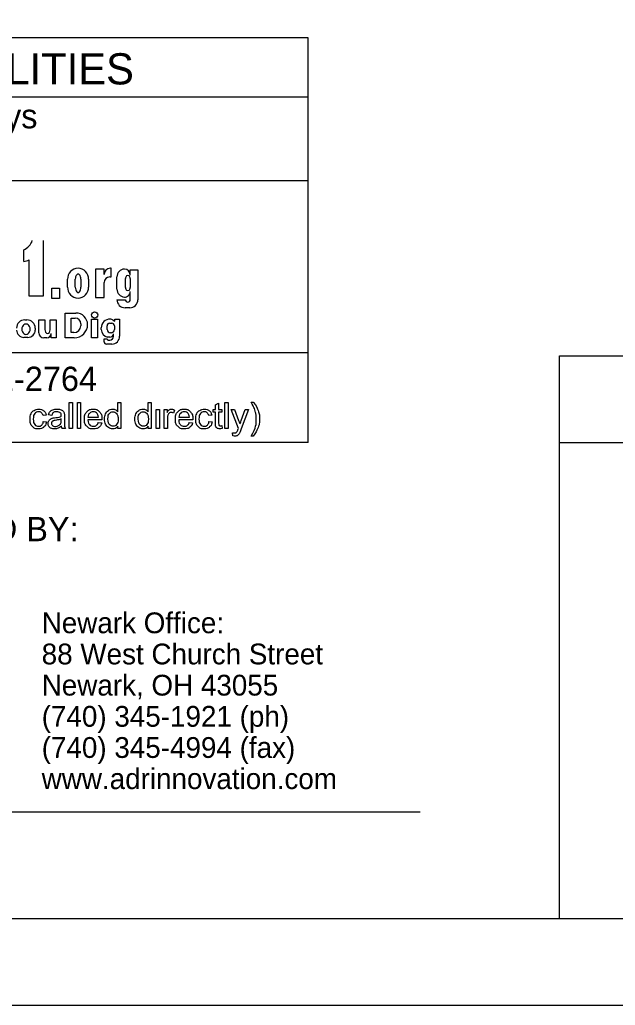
# Model space of a CAD drawing. Extents: x -6.4 to 34, y -1.2 to 22.
# Drawn here: x 5.59 to 9.02, y 0 to 5.69 of the extents above; entities that cross this region are included whole.
import ezdxf

# ---------------------------------------------------------------- set-up
doc = ezdxf.new("R2010")
doc.units = 0
for name, color, linetype in [('GM_X_County', 7, 'Continuous'), ('GM_X_Section', 7, 'Continuous'), ('GM_X_Township', 7, 'Continuous')]:
    doc.layers.add(name, color=color, linetype=linetype)

msp = doc.modelspace()

# ---------------------------------------------------------------- linework, layer by layer
at = {"layer": 'GM_X_County'}
msp.add_lwpolyline([(1.5, 21.5), (33.5, 21.5), (33.5, 0.5), (1.5, 0.5)], close=True, dxfattribs=at)
at = {"layer": 'GM_X_Section'}
msp.add_lwpolyline([(0, 0), (34, 0), (34, 22), (0, 22)], close=True, dxfattribs=at)
at = {"layer": 'GM_X_Township'}
for p, q in [((7.25, 5.5875), (3, 5.5875)), ((7.25, 3.25), (7.25, 5.5875)), ((3, 5.2459), (7.25, 5.2459)), ((3, 4.7625), (7.25, 4.7625)), ((5.72, 4.4158), (5.72, 4.0959)), ((5.6084, 4.2951), (5.6084, 4.3633)), ((5.6407, 4.0959), (5.6407, 4.3045)), ((6.0718, 4.2507), (6.023, 4.2507)), ((6.023, 4.2507), (6.023, 4.0878)), ((6.0718, 4.2192), (6.0718, 4.2507)), ((6.1125, 4.2559), (6.1085, 4.2559)), ((6.1125, 4.206), (6.1125, 4.2559)), ((6.2233, 4.2166), (6.2233, 4.2476)), ((6.2233, 4.2476), (6.2669, 4.2476)), ((6.2669, 4.2476), (6.2669, 4.0747)), ((5.8609, 4.1476), (5.8609, 4.193)), ((5.906, 4.1468), (5.906, 4.193)), ((5.9381, 4.193), (5.9381, 4.1468)), ((5.9831, 4.193), (5.9831, 4.1476)), ((6.0718, 4.0878), (6.0718, 4.173)), ((6.1048, 4.206), (6.1125, 4.206)), ((6.1464, 4.1361), (6.1464, 4.2058)), ((6.1948, 4.1455), (6.1948, 4.1965)), ((6.2233, 4.1965), (6.2233, 4.1455)), ((5.7681, 4.1409), (5.7681, 4.0808)), ((6.2233, 4.0747), (6.2233, 4.1211)), ((5.72, 4.0959), (5.6407, 4.0959)), ((6.023, 4.0878), (6.0718, 4.0878)), ((6.1464, 4.0747), (6.1948, 4.0747)), ((5.8468, 3.9978), (5.9091, 3.9978)), ((5.8468, 3.855), (5.8468, 3.9978)), ((6.2201, 4.028), (6.1932, 4.028)), ((5.615, 3.9579), (5.6272, 3.9579)), ((5.6952, 3.9579), (5.7299, 3.9579)), ((5.6952, 3.8834), (5.6952, 3.9579)), ((5.7299, 3.9579), (5.7299, 3.9026)), ((5.7613, 3.9009), (5.7613, 3.9579)), ((5.7613, 3.9579), (5.7961, 3.9579)), ((5.7961, 3.9579), (5.7961, 3.855)), ((5.8828, 3.8844), (5.8828, 3.9685)), ((5.8828, 3.9685), (5.9053, 3.9685)), ((5.9379, 3.9358), (5.9379, 3.9239)), ((5.9995, 3.9621), (6.0351, 3.9621)), ((5.9995, 3.855), (5.9995, 3.9621)), ((6.0351, 3.9621), (6.0351, 3.855)), ((6.1041, 3.9391), (6.1168, 3.9391)), ((6.1246, 3.9565), (6.1332, 3.9499)), ((6.1332, 3.9625), (6.162, 3.9625)), ((6.1332, 3.9499), (6.1332, 3.9625)), ((6.1332, 3.9625), (6.162, 3.9625)), ((6.162, 3.9625), (6.162, 3.8639)), ((5.675, 3.9101), (5.675, 3.8993)), ((5.7664, 3.855), (5.7664, 3.8791)), ((5.8984, 3.8844), (5.8828, 3.8844)), ((6.056, 3.9025), (6.056, 3.9126)), ((6.0895, 3.9033), (6.0895, 3.9245)), ((6.1122, 3.8839), (6.1088, 3.8839)), ((6.1264, 3.8629), (6.1264, 3.8782)), ((6.1315, 3.9245), (6.1315, 3.9033)), ((5.6322, 3.8566), (5.61, 3.8566)), ((5.7424, 3.855), (5.7236, 3.855)), ((5.7961, 3.855), (5.7664, 3.855)), ((5.9004, 3.855), (5.8468, 3.855)), ((6.0351, 3.855), (5.9995, 3.855)), ((6.0725, 3.8317), (6.0725, 3.8487)), ((6.0725, 3.8487), (6.0895, 3.8487)), ((6.1167, 3.8186), (6.0856, 3.8186)), ((6.106, 3.8578), (6.0923, 3.8578)), ((6.0963, 3.8417), (6.1052, 3.8417)), ((7.25, 3.7678), (3, 3.7678)), ((8.7, 0.5), (8.7, 3.75)), ((8.7, 3.75), (11.5, 3.75)), ((7.25, 3.25), (3, 3.25)), ((8.7, 3.25), (11.5, 3.25)), ((2.6879, 1.1163), (7.8956, 1.1163))]:
    msp.add_line(p, q, dxfattribs=at)
msp.add_lwpolyline([(5.7705, 4.1409), (5.8146, 4.1409), (5.8146, 4.0808), (5.7705, 4.0808)], close=True, dxfattribs=at)
for points in [[(5.8715, 3.3311), (5.8715, 3.4813), (5.89, 3.4813), (5.89, 3.3311), (5.8715, 3.3311)], [(5.9181, 3.3311), (5.9181, 3.4813), (5.9365, 3.4813), (5.9365, 3.3311), (5.9181, 3.3311)], [(6.151, 3.4274), (6.151, 3.4813), (6.1694, 3.4813), (6.1694, 3.3311), (6.1524, 3.3311)], [(6.3259, 3.4274), (6.3259, 3.4813), (6.3443, 3.4813), (6.3443, 3.3311), (6.3273, 3.3311)], [(6.7145, 3.363), (6.7145, 3.4256), (6.7009, 3.4256), (6.7009, 3.4399), (6.7145, 3.4399), (6.7145, 3.4669), (6.733, 3.4779), (6.733, 3.4399), (6.7514, 3.4399), (6.7514, 3.4256), (6.733, 3.4256), (6.733, 3.3619)], [(6.769, 3.3311), (6.769, 3.4813), (6.7874, 3.4813), (6.7874, 3.3311), (6.769, 3.3311)], [(6.9198, 3.4838), (6.933, 3.4838)], [(6.3734, 3.3311), (6.3734, 3.4399), (6.3918, 3.4399), (6.3918, 3.3311), (6.3734, 3.3311)], [(6.4196, 3.3311), (6.4196, 3.4399), (6.4362, 3.4399), (6.4362, 3.4234)], [(6.4787, 3.4365), (6.4722, 3.4194)], [(6.8468, 3.331), (6.8055, 3.4399), (6.8254, 3.4399), (6.848, 3.3771)], [(6.8635, 3.3765), (6.8868, 3.4399), (6.9052, 3.4399), (6.8639, 3.3292)], [(5.7379, 3.4079), (5.7199, 3.4051)], [(5.7215, 3.3709), (5.7396, 3.3685)], [(5.7704, 3.4064), (5.7523, 3.4088)], [(5.8247, 3.3789), (5.8248, 3.3857)], [(5.8434, 3.4013), (5.8434, 3.3767)], [(6.0591, 3.3808), (5.978, 3.3808)], [(5.979, 3.3959), (6.0398, 3.3959)], [(6.0396, 3.3662), (6.0586, 3.3638)], [(6.438, 3.3881), (6.438, 3.3311), (6.4196, 3.3311)], [(6.5836, 3.3808), (6.5025, 3.3808)], [(6.5035, 3.3959), (6.5643, 3.3959)], [(6.5641, 3.3662), (6.5831, 3.3638)], [(6.6937, 3.4079), (6.6757, 3.4051)], [(6.6773, 3.3709), (6.6954, 3.3685)], [(5.8492, 3.3311), (5.83, 3.3311)], [(6.1524, 3.3311), (6.1524, 3.3448)], [(6.3273, 3.3311), (6.3273, 3.3448)], [(6.7514, 3.3475), (6.754, 3.3312)], [(6.8152, 3.2893), (6.8132, 3.3066)], [(6.933, 3.2869), (6.9198, 3.2869)]]:
    msp.add_lwpolyline(points, dxfattribs=at)
msp.add_circle((6.0177, 3.9864), 0.0177, dxfattribs=at)
for centre, radius, start, end in [((5.5744, 4.445), 0.0885, 292.5572, 340.7355), ((5.6004, 4.3833), 0.0885, 275.1733, 297.0931), ((5.9249, 4.193), 0.064, 92.5886, 180), ((5.9191, 4.193), 0.064, 0, 87.4114), ((6.1085, 4.2192), 0.0367, 90, 180), ((6.1923, 4.2058), 0.0459, 92.6865, 180), ((6.1883, 4.2166), 0.0351, 0, 86.9262), ((6.1048, 4.173), 0.033, 90, 180), ((5.9249, 4.1476), 0.064, 180, 267.4114), ((5.9191, 4.1476), 0.064, 272.5886, 0), ((6.1927, 4.1361), 0.0463, 180, 265.7132), ((6.1921, 4.1211), 0.0313, 264.7825, 0), ((6.1932, 4.0747), 0.0468, 180, 270), ((6.2201, 4.0747), 0.0468, 270, 0), ((5.9091, 3.9295), 0.0682, 0.9944, 90), ((5.615, 3.9101), 0.0478, 90, 180), ((5.6272, 3.9101), 0.0478, 0, 90), ((5.9004, 3.932), 0.0769, 270, 359.0635), ((5.9053, 3.9358), 0.0327, 0, 90), ((6.1059, 3.9126), 0.0499, 89.0934, 180), ((6.1041, 3.9245), 0.0146, 90, 180), ((6.1073, 3.9342), 0.0283, 52.1415, 91.2046), ((6.1168, 3.9245), 0.0146, 0, 90), ((5.61, 3.8993), 0.0428, 180, 270), ((5.6322, 3.8993), 0.0428, 270, 0), ((5.7236, 3.8834), 0.0284, 180, 270), ((5.7424, 3.8791), 0.024, 270, 0), ((5.8984, 3.9239), 0.0395, 270, 0), ((6.1016, 3.9025), 0.0457, 180, 258.2203), ((6.1088, 3.9033), 0.0193, 180, 270), ((6.106, 3.8781), 0.0203, 270, 0), ((6.1122, 3.9033), 0.0193, 270, 0), ((6.0856, 3.8317), 0.0131, 180, 270), ((6.0963, 3.8485), 0.00682, 180, 270), ((6.1052, 3.8629), 0.0212, 270, 0), ((6.1167, 3.8639), 0.0453, 270, 0)]:
    msp.add_arc(centre, radius, start, end, dxfattribs=at)
for centre, major_axis, ratio, start_param, end_param in [((5.9221, 4.193), (0, 0.0291), 0.553236, 4.712389, 7.853982), ((6.2091, 4.1965), (0, 0.0184), 0.777179, 4.712389, 7.853982), ((5.9221, 4.1468), (0, 0.0308), 0.522014, 1.570796, 4.712389), ((6.2091, 4.1455), (0, 0.0184), 0.777179, 1.570796, 4.712389), ((6.2091, 4.0747), (0.0143, 0), 0.959012, 3.141593, 6.283185), ((5.6216, 3.9047), (0, 0.029), 0.832186, 4.712389, 7.853982), ((5.6216, 3.9047), (0, 0.0302), 0.797287, 1.570796, 4.712389), ((5.7456, 3.9033), (-0.0011, 0.0231), 0.679042, 1.570796, 4.575961)]:
    msp.add_ellipse(centre, major_axis=major_axis, ratio=ratio, start_param=start_param, end_param=end_param, dxfattribs=at)
for points, degree in [([(6.9198, 3.2869), (6.9504, 3.3361), (6.9504, 3.3853), (6.9504, 3.4046), (6.946, 3.4235), (6.9425, 3.4389), (6.9363, 3.453), (6.9323, 3.4623), (6.9198, 3.4838)], 3), ([(6.933, 3.4838), (6.9523, 3.4581), (6.9615, 3.4322), (6.9694, 3.4098), (6.9694, 3.3854), (6.9694, 3.3578), (6.9588, 3.332), (6.9482, 3.3062), (6.933, 3.2869)], 3), ([(5.7396, 3.3685), (5.7366, 3.3498), (5.7244, 3.3393), (5.7121, 3.3287), (5.6943, 3.3287), (5.672, 3.3287), (5.6584, 3.3433), (5.6448, 3.3579), (5.6448, 3.3851), (5.6448, 3.4027), (5.6507, 3.4159), (5.6565, 3.4291), (5.6684, 3.4357), (5.6804, 3.4423), (5.6944, 3.4423), (5.7122, 3.4423), (5.7234, 3.4334), (5.7347, 3.4244), (5.7379, 3.4079)], 3), ([(5.7199, 3.4051), (5.7173, 3.4161), (5.7108, 3.4217), (5.7043, 3.4272), (5.6951, 3.4272), (5.6812, 3.4272), (5.6725, 3.4172), (5.6638, 3.4072), (5.6638, 3.3856), (5.6638, 3.3637), (5.6722, 3.3537), (5.6806, 3.3438), (5.6942, 3.3438), (5.705, 3.3438), (5.7123, 3.3505), (5.7196, 3.3571), (5.7215, 3.3709)], 3), ([(5.8263, 3.3445), (5.816, 3.3358), (5.8066, 3.3323), (5.7971, 3.3287), (5.7863, 3.3287), (5.7683, 3.3287), (5.7587, 3.3374), (5.7491, 3.3462), (5.7491, 3.3598), (5.7491, 3.3678), (5.7527, 3.3744), (5.7564, 3.381), (5.7622, 3.385), (5.7681, 3.389), (5.7755, 3.391), (5.7809, 3.3924), (5.7919, 3.3938), (5.8142, 3.3964), (5.8247, 3.4001), (5.8248, 3.4039), (5.8248, 3.4049), (5.8248, 3.4162), (5.8196, 3.4209), (5.8126, 3.4271), (5.7987, 3.4271), (5.7857, 3.4271), (5.7795, 3.4226), (5.7733, 3.418), (5.7704, 3.4064)], 3), ([(5.7523, 3.4088), (5.7547, 3.4204), (5.7604, 3.4275), (5.766, 3.4346), (5.7767, 3.4385), (5.7873, 3.4423), (5.8013, 3.4423), (5.8152, 3.4423), (5.8239, 3.4391), (5.8326, 3.4358), (5.8367, 3.4308), (5.8408, 3.4258), (5.8425, 3.4183), (5.8434, 3.4135), (5.8434, 3.4013)], 3), ([(6.0586, 3.3638), (6.0541, 3.3471), (6.0419, 3.3379), (6.0297, 3.3287), (6.0108, 3.3287), (5.9869, 3.3287), (5.973, 3.3434), (5.959, 3.3581), (5.959, 3.3846), (5.959, 3.412), (5.9731, 3.4272), (5.9872, 3.4423), (6.0098, 3.4423), (6.0316, 3.4423), (6.0454, 3.4275), (6.0592, 3.4126), (6.0592, 3.3857), (6.0592, 3.384), (6.0591, 3.3808)], 3), ([(6.0398, 3.3959), (6.0385, 3.4097), (6.0328, 3.4165), (6.024, 3.4272), (6.01, 3.4272), (5.9972, 3.4272), (5.9886, 3.4187), (5.9799, 3.4102), (5.979, 3.3959)], 3), ([(6.1524, 3.3448), (6.142, 3.3287), (6.122, 3.3287), (6.1089, 3.3287), (6.098, 3.3359), (6.0871, 3.343), (6.0811, 3.3559), (6.0751, 3.3687), (6.0751, 3.3854), (6.0751, 3.4017), (6.0806, 3.415), (6.086, 3.4282), (6.0968, 3.4353), (6.1077, 3.4423), (6.1211, 3.4423), (6.1309, 3.4423), (6.1385, 3.4382), (6.1462, 3.4341), (6.151, 3.4274)], 3), ([(6.0941, 3.3854), (6.0941, 3.3645), (6.1029, 3.3542), (6.1118, 3.3438), (6.1237, 3.3438), (6.1358, 3.3438), (6.1443, 3.3537), (6.1527, 3.3636), (6.1527, 3.3839), (6.1527, 3.4062), (6.1441, 3.4167), (6.1355, 3.4271), (6.1229, 3.4271), (6.1106, 3.4271), (6.1024, 3.4171), (6.0941, 3.407), (6.0941, 3.3854)], 3), ([(6.3273, 3.3448), (6.3169, 3.3287), (6.2968, 3.3287), (6.2838, 3.3287), (6.2729, 3.3359), (6.262, 3.343), (6.256, 3.3559), (6.25, 3.3687), (6.25, 3.3854), (6.25, 3.4017), (6.2554, 3.415), (6.2608, 3.4282), (6.2717, 3.4353), (6.2825, 3.4423), (6.2959, 3.4423), (6.3057, 3.4423), (6.3134, 3.4382), (6.3211, 3.4341), (6.3259, 3.4274)], 3), ([(6.269, 3.3854), (6.269, 3.3645), (6.2778, 3.3542), (6.2866, 3.3438), (6.2986, 3.3438), (6.3107, 3.3438), (6.3191, 3.3537), (6.3276, 3.3636), (6.3276, 3.3839), (6.3276, 3.4062), (6.319, 3.4167), (6.3104, 3.4271), (6.2978, 3.4271), (6.2855, 3.4271), (6.2772, 3.4171), (6.269, 3.407), (6.269, 3.3854)], 3), ([(6.4362, 3.4234), (6.4425, 3.435), (6.4479, 3.4387), (6.4533, 3.4423), (6.4597, 3.4423), (6.469, 3.4423), (6.4787, 3.4365)], 3), ([(6.4722, 3.4194), (6.4655, 3.4233), (6.4588, 3.4233), (6.4527, 3.4233), (6.4479, 3.4197), (6.4432, 3.4161), (6.4411, 3.4096), (6.438, 3.3998), (6.438, 3.3881)], 3), ([(6.5831, 3.3638), (6.5786, 3.3471), (6.5664, 3.3379), (6.5542, 3.3287), (6.5353, 3.3287), (6.5114, 3.3287), (6.4974, 3.3434), (6.4835, 3.3581), (6.4835, 3.3846), (6.4835, 3.412), (6.4976, 3.4272), (6.5117, 3.4423), (6.5343, 3.4423), (6.5561, 3.4423), (6.5699, 3.4275), (6.5837, 3.4126), (6.5837, 3.3857), (6.5837, 3.384), (6.5836, 3.3808)], 3), ([(6.5643, 3.3959), (6.563, 3.4097), (6.5573, 3.4165), (6.5485, 3.4272), (6.5344, 3.4272), (6.5217, 3.4272), (6.5131, 3.4187), (6.5044, 3.4102), (6.5035, 3.3959)], 3), ([(6.6954, 3.3685), (6.6924, 3.3498), (6.6802, 3.3393), (6.668, 3.3287), (6.6501, 3.3287), (6.6278, 3.3287), (6.6142, 3.3433), (6.6007, 3.3579), (6.6007, 3.3851), (6.6007, 3.4027), (6.6065, 3.4159), (6.6123, 3.4291), (6.6243, 3.4357), (6.6362, 3.4423), (6.6503, 3.4423), (6.668, 3.4423), (6.6793, 3.4334), (6.6905, 3.4244), (6.6937, 3.4079)], 3), ([(6.6757, 3.4051), (6.6732, 3.4161), (6.6667, 3.4217), (6.6602, 3.4272), (6.651, 3.4272), (6.6371, 3.4272), (6.6284, 3.4172), (6.6197, 3.4072), (6.6197, 3.3856), (6.6197, 3.3637), (6.6281, 3.3537), (6.6365, 3.3438), (6.65, 3.3438), (6.6608, 3.3438), (6.6681, 3.3505), (6.6754, 3.3571), (6.6773, 3.3709)], 3), ([(5.8248, 3.3857), (5.8148, 3.3816), (5.7947, 3.3787), (5.7833, 3.3771), (5.7786, 3.375), (5.7739, 3.373), (5.7713, 3.3691), (5.7688, 3.3651), (5.7688, 3.3603), (5.7688, 3.3529), (5.7743, 3.348), (5.7799, 3.3431), (5.7907, 3.3431), (5.8013, 3.3431), (5.8096, 3.3478), (5.8179, 3.3524), (5.8218, 3.3605), (5.8247, 3.3668), (5.8247, 3.3789)], 3), ([(5.8434, 3.3767), (5.8434, 3.351), (5.8446, 3.3442), (5.8457, 3.3374), (5.8492, 3.3311)], 3), ([(5.978, 3.3808), (5.979, 3.3629), (5.9881, 3.3533), (5.9972, 3.3438), (6.0109, 3.3438), (6.021, 3.3438), (6.0282, 3.3492), (6.0354, 3.3545), (6.0396, 3.3662)], 3), ([(6.5025, 3.3808), (6.5035, 3.3629), (6.5126, 3.3533), (6.5217, 3.3438), (6.5354, 3.3438), (6.5455, 3.3438), (6.5527, 3.3492), (6.5599, 3.3545), (6.5641, 3.3662)], 3), ([(6.754, 3.3312), (6.7462, 3.3296), (6.7401, 3.3296), (6.7301, 3.3296), (6.7246, 3.3328), (6.719, 3.336), (6.7168, 3.3412), (6.7145, 3.3463), (6.7145, 3.363)], 3), ([(6.733, 3.3619), (6.733, 3.354), (6.7339, 3.3517), (6.7349, 3.3494), (6.7371, 3.3481), (6.7393, 3.3468), (6.7433, 3.3468), (6.7464, 3.3468), (6.7514, 3.3475)], 3), ([(6.848, 3.3771), (6.8524, 3.3652), (6.8559, 3.352), (6.8591, 3.3644), (6.8635, 3.3765)], 3), ([(5.83, 3.3311), (5.8271, 3.3368), (5.8263, 3.3445)], 2), ([(6.8132, 3.3066), (6.8192, 3.305), (6.8237, 3.305), (6.8299, 3.305), (6.8335, 3.3071), (6.8372, 3.3091), (6.8396, 3.3128), (6.8413, 3.3156), (6.8452, 3.3265), (6.8457, 3.328), (6.8468, 3.331)], 3), ([(6.8639, 3.3292), (6.8573, 3.3113), (6.8536, 3.3046), (6.8486, 3.2955), (6.8423, 3.2913), (6.8359, 3.287), (6.8271, 3.287), (6.8218, 3.287), (6.8152, 3.2893)], 3)]:
    msp.add_open_spline(points, degree=degree, dxfattribs=at)

# ---------------------------------------------------------------- texts
for s, height, p in [('UNDERGROUND UTILITIES', 0.18, (3.1282, 5.3178)), ('Contact Two Working Days', 0.14, (3.4196, 5.0643)), ('OHIO811, 8-1-1, or 1-800-362-2764', 0.14, (3.0445, 3.5478)), ('PLAN PREPARED BY:', 0.14, (4.0001, 2.68)), ('Newark Office:', 0.12, (5.7122, 2.1486)), ('88 West Church Street', 0.12, (5.7122, 1.9686)), ('Newark, OH 43055', 0.12, (5.7122, 1.7886)), ('(740) 345-1921 (ph)', 0.12, (5.7122, 1.6086)), ('(740) 345-4994 (fax)', 0.12, (5.7122, 1.4286)), ('www.adrinnovation.com', 0.12, (5.7122, 1.2486))]:
    msp.add_text(s, height=height, dxfattribs=at).set_placement(p)

doc.saveas('drawing.dxf')
